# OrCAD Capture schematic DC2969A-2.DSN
size B
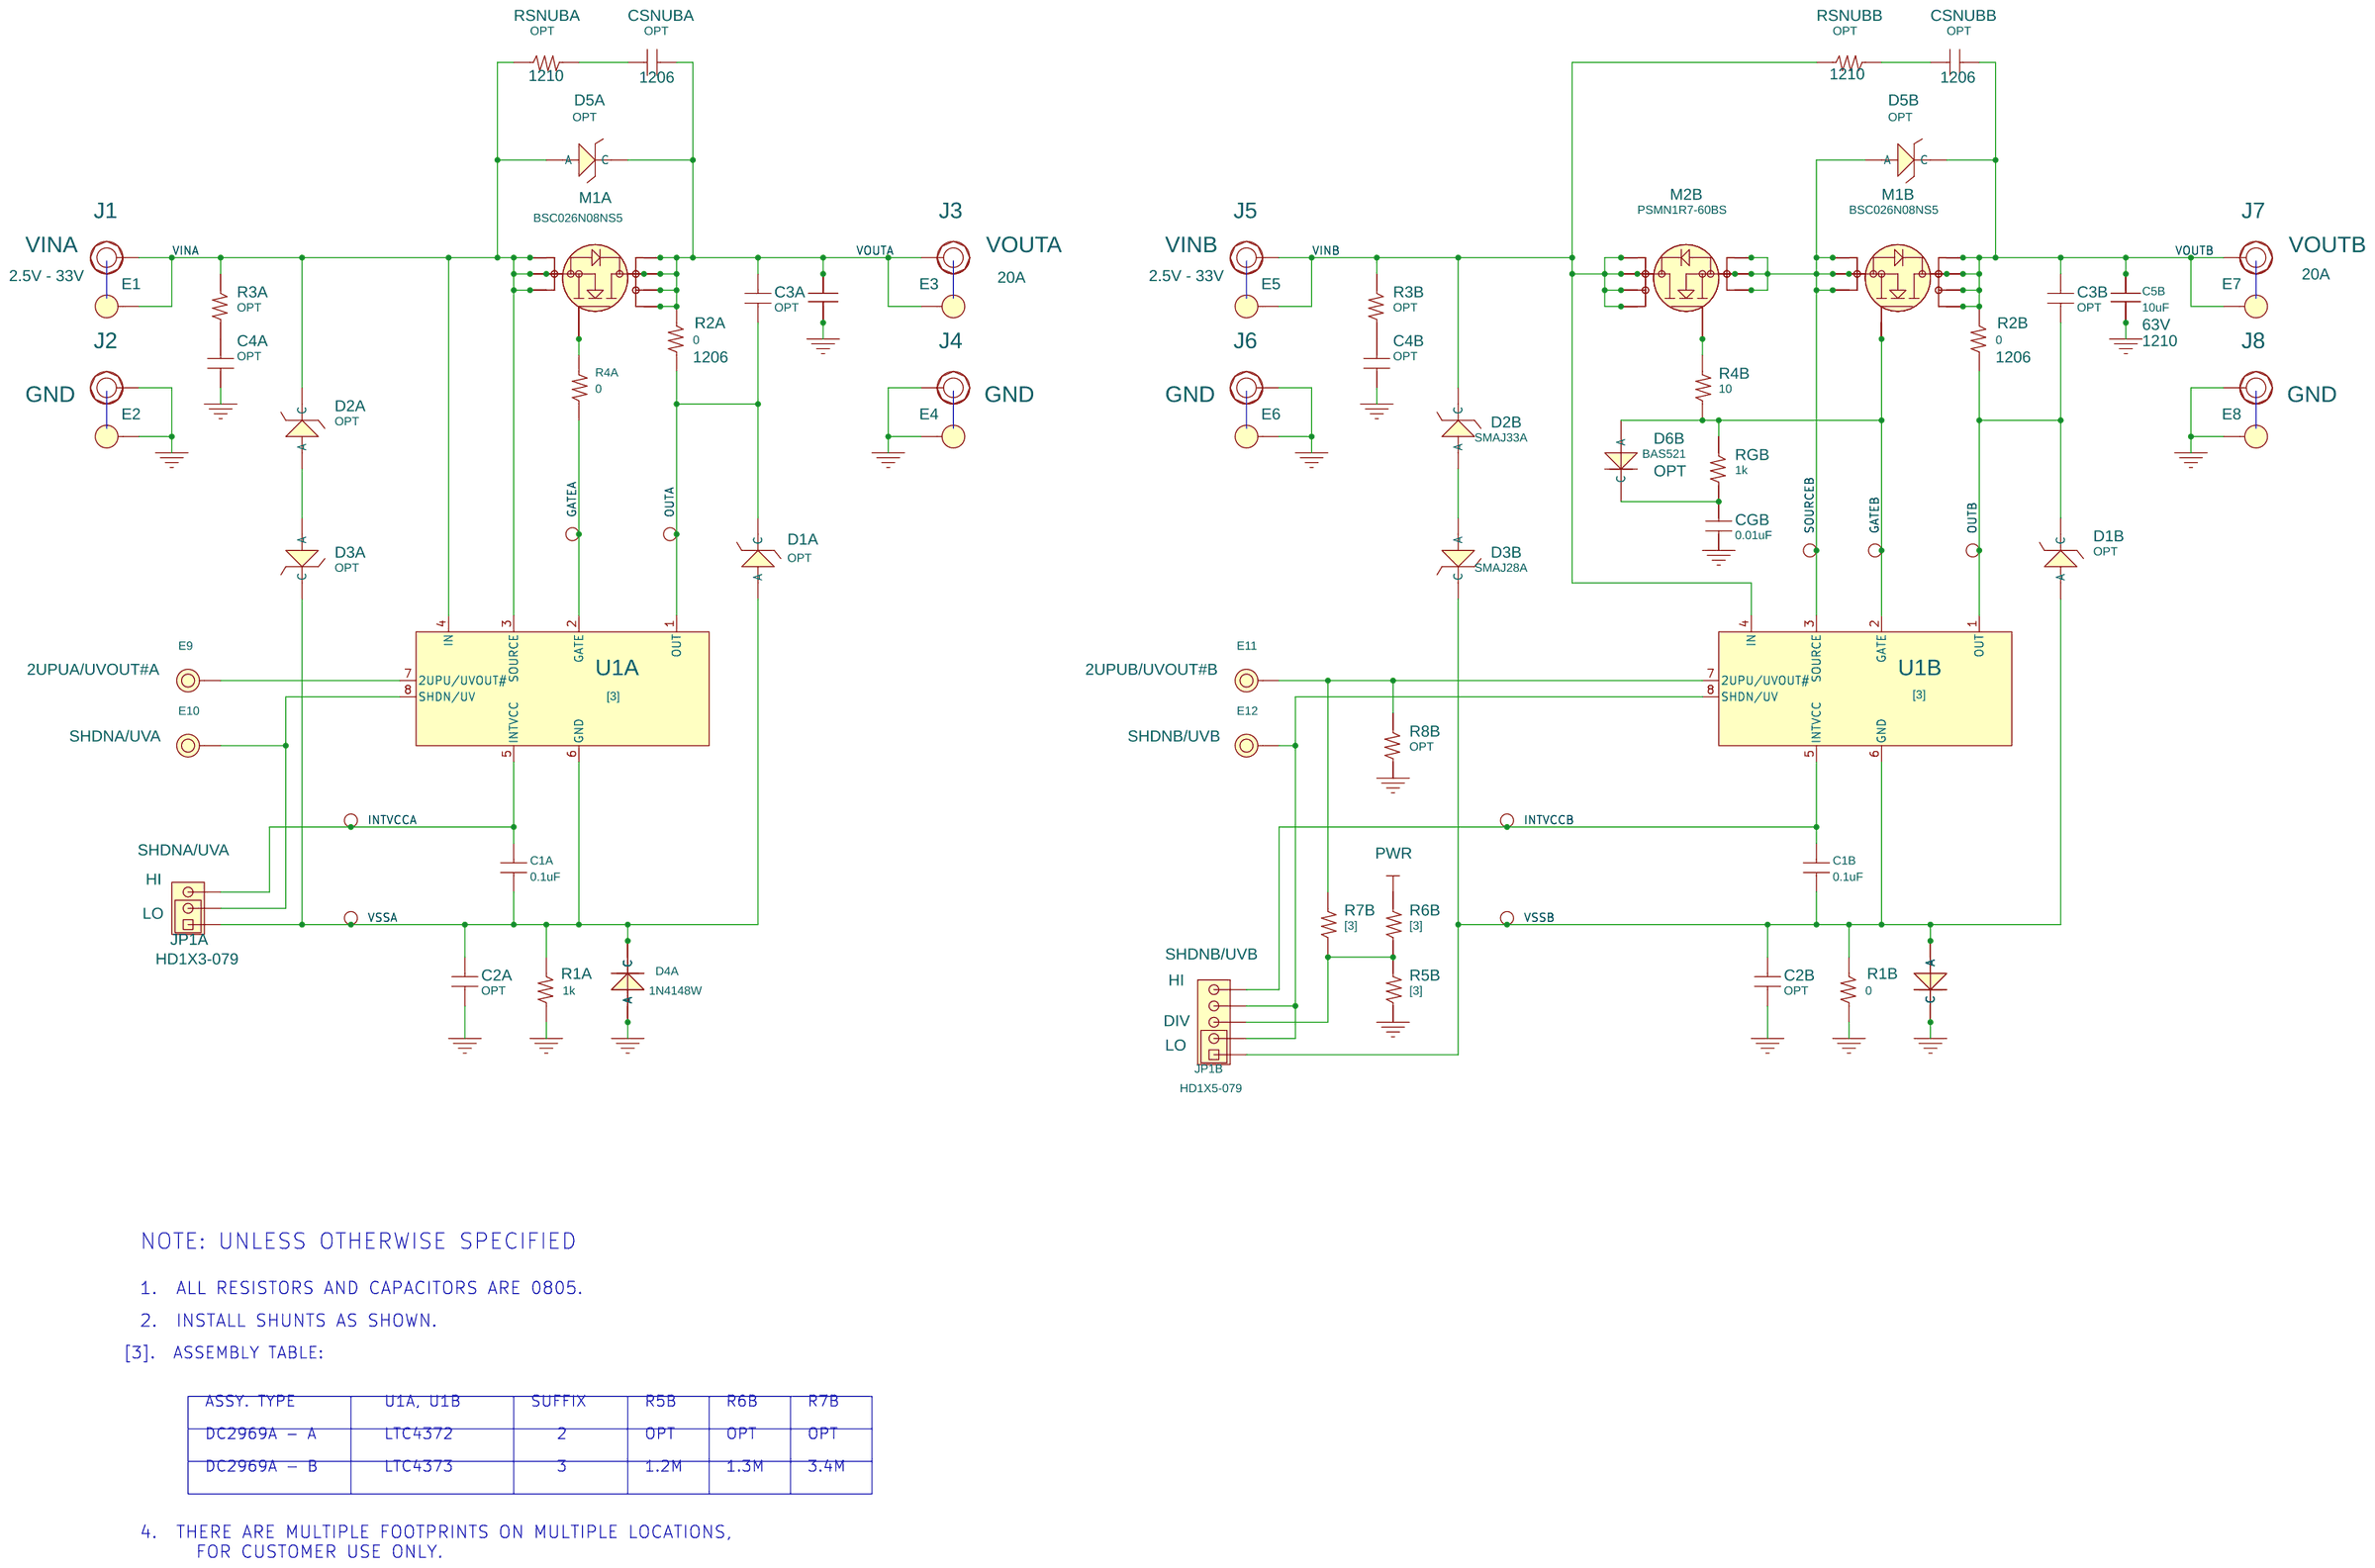
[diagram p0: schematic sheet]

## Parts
C1A  0.1uF  [CC0805N]
C1B  0.1uF  [CC0805N]
C2A  OPT  [0805]
C2B  OPT  [0805]
C3A  OPT  [0805]
C3B  OPT  [0805]
C4A  OPT  [0805]
C4B  OPT  [0805]
C5A  10uF  [CC1210N]
C5AA  OPT  [1210-NS]
C5B  10uF  [CC1210N]
C5BB  OPT  [1210-NS]
CGB  0.01uF  [0805]
CSNUBA  OPT  [1206]
CSNUBB  OPT  [1206]
D1A  OPT  [SMA-DIODE]
D1B  OPT  [SMA-DIODE]
D2A  OPT  [SMA-DIODE]
D2B  SMAJ33A  [SMA-DIODE]
D3A  OPT  [SMA-DIODE]
D3B  SMAJ28A  [SMA-DIODE]
D4A  1N4148W  [SOD-123N]
D4AA  1N4148W  [SMA-DIODE-NS]
D4B  1N4148W  [SOD-123N]
D4BB  1N4148W  [SMA-DIODE-NS]
D5A  OPT  [SMA-DIODE]
D5B  OPT  [SMA-DIODE]
D6B  BAS521  [SOD523]
E1  MILL-MAX-2501  [MILL-MAX-2501]
E2  MILL-MAX-2501  [MILL-MAX-2501]
E3  MILL-MAX-2501  [MILL-MAX-2501]
E4  MILL-MAX-2501  [MILL-MAX-2501]
E5  MILL-MAX-2501  [MILL-MAX-2501]
E6  MILL-MAX-2501  [MILL-MAX-2501]
E7  MILL-MAX-2501  [MILL-MAX-2501]
E8  MILL-MAX-2501  [MILL-MAX-2501]
E9  MIL-MAX-2308  [MILL-MAX-2308]
E10  MIL-MAX-2308  [MILL-MAX-2308]
E11  MIL-MAX-2308  [MILL-MAX-2308]
E12  MIL-MAX-2308  [MILL-MAX-2308]
GATEA  E-100-25  [PAD100-25]
GATEB  E-100-25  [PAD100-25]
INTVCCA  E-100-25  [PAD100-25]
INTVCCB  E-100-25  [PAD100-25]
J1  BANANA JACK  [KEY-575-4]
J2  BANANA JACK  [KEY-575-4]
J3  BANANA JACK  [KEY-575-4]
J4  BANANA JACK  [KEY-575-4]
J5  BANANA JACK  [KEY-575-4]
J6  BANANA JACK  [KEY-575-4]
J7  BANANA JACK  [KEY-575-4]
J8  BANANA JACK  [KEY-575-4]
JP1A  HDR.  [HD1X3-079]
JP1B  HD1X5-079  [HD1X5-079]
M1A  BSC026N08NS5  [PG-TDSON8]
M1A-B-SO8  BSC026N08NS5  [PG-TDSON8-NS]
M1A-OPT-B  D2PAK-DPAK-SO8POWERPAK  [D2PAK-DPAK-SO8POWERPAK-NS]
M1A-OPT-T  D2PAK-DPAK-SO8POWERPAK  [D2PAK-DPAK-SO8POWERPAK-NS]
M1B  BSC026N08NS5  [PG-TDSON8]
M1B-B-SO8  BSC026N08NS5  [PG-TDSON8-NS]
M1B-OPT-B  D2PAK-DPAK-SO8POWERPAK  [D2PAK-DPAK-SO8POWERPAK-NS]
M1B-OPT-T  D2PAK-DPAK-SO8POWERPAK  [D2PAK-DPAK-SO8POWERPAK-NS]
M2B  PSMN1R7-60BS  [D2PAK]
M2B-B-SO8  BSC026N08NS5  [PG-TDSON8-NS]
M2B-OPT-B  D2PAK-DPAK-SO8POWERPAK  [D2PAK-DPAK-SO8POWERPAK-NS]
M2B-OPT-T  D2PAK-DPAK-SO8POWERPAK  [D2PAK-DPAK-SO8POWERPAK-NS]
M2B-T-SO8  BSC026N08NS5  [PG-TDSON8-NS]
OUTA  E-100-25  [PAD100-25]
OUTB  E-100-25  [PAD100-25]
R1A  1k  [1206-0805]
R1B  0  [1206-0805]
R2A  0  [1206]
R2B  0  [1206]
R3A  OPT  [0805]
R3B  OPT  [0805]
R4A  0  [CR0805N]
R4B  10  [0805]
R5B  [3]  [0805]
R6B  [3]  [0805]
R7B  [3]  [0805]
R8B  OPT  [0805]
RGB  1k  [0805]
RSNUBA  OPT  [1210]
RSNUBB  OPT  [1210]
SMAA  OPT  [SMA-DIODE]
SMAB  OPT  [SMA-DIODE]
SOURCEB  E-100-25  [PAD100-25]
U1A  [3]  [MS8]
U1B  [3]  [MS8]
VSSA  E-100-25  [PAD100-25]
VSSB  E-100-25  [PAD100-25]

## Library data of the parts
C1A C1B = CAP_ALT: CAP.,0.1uF,X7R,25V,20%,0805; CLASS: DISCRETE; Dielectric Type: X7R; FPLIST: CC0805N,CC0805L,CC0805M; Inventory Qty: 198; Manufacturer: AVX; Manufacturer PN: 08053C104MAT2A; PART_NUMBER: 150-0305; Package Size: 0805; Rated Voltage: 25V; Tolerance: 20%
C2A C2B C3A C3B C4A C4B = CAP-NP: CAP., OPTION, 0805; CLASS: DISCRETE; FPLIST: CC0805N,CC0805L,CC0805M; PART_NUMBER: 150-3036; Package Type: SMD
C5A C5B = CAP: CAP.,10uF,X7R,63V,10%,1210; CLASS: DISCRETE; Dielectric Type: X7R; FPLIST: CC1210N,CC1210L,CC1210M; Inventory Qty: 6452; Manufacturer: Murata; Manufacturer PN: GRM32ER71J106KA12L; PART_NUMBER: 150-1321; Package Size: 1210; Rated Voltage: 63V; Tolerance: 10%
C5AA C5BB = CAP: CAP., OPTION, 1210; CLASS: DISCRETE; FPLIST: CC1210N,CC1210L,CC1210M; PART_NUMBER: 150-3035; Package Size: 1210; Package Type: SMD
CGB = CAP-NP: CAP.,0.01uF,X7R,100V,10%,0805; CLASS: DISCRETE; Dielectric Type: X7R; FPLIST: CC0805N,CC0805L,CC0805M; Inventory Qty: 13000; Manufacturer: AVX; Manufacturer PN: 08051C103KAT2A; PART_NUMBER: 150-2308; Package Type: SMD; Rated Voltage: 100V; Tolerance: 10%
CSNUBA CSNUBB = CAP-NP: CAP., OPTION, 1206; CLASS: DISCRETE; FPLIST: CC1206N,CC1206L,CC1206M; PART_NUMBER: 150-3160; Package Type: SMD
D1A D1B = DIODE_TVS_B: DIODE,TVS, SINGLE, UNI-DIRECT,33V,400W,SMA; CLASS: DISCRETE; FPLIST: SMA-N,SMA-L,SMA-M,SMA; Manufacturer: DIODES INC.; Manufacturer PN: SMAJ33A; Max Forward Current or Rated Power: 400W; PART_NUMBER: SMAJ33A; Package Type: SMA; Rated Voltage or Zener Voltage: 33V
D2A D3A D5A D5B = DIODE_TVS_B: DIODE, OPTION, TVS, SMA; CLASS: DISCRETE; FPLIST: SMA-N,SMA-L,SMA-M,SMA; PART_NUMBER: 210-0215; Package Type: SMA
D2B = DIODE_TVS_B: DIODE,TVS, SINGLE, UNI-DIRECT,33V,400W,SMA; CLASS: DISCRETE; FPLIST: SMA-N,SMA-L,SMA-M,SMA; Manufacturer: DIODES INC.; Max Forward Current or Rated Power: 400W; Package Type: SMA; Rated Voltage or Zener Voltage: 33V
D3B = DIODE_TVS_B: DIODE, OPTION, TVS, SMA; CLASS: DISCRETE; FPLIST: SMA-N,SMA-L,SMA-M,SMA; Package Type: SMA
D4A = DIODE_A: DIODE,SWITCHING,100V,300mA,SOD-123; CLASS: DISCRETE; FPLIST: SOD-123N,SOD-123L,SOD-123M; Inventory Qty: 3450; Manufacturer: DIODES INC.; Manufacturer PN: 1N4148W-7-F; Max Forward Current or Rated Power: 200mW; PART_NUMBER: 210-0214; Package Type: SOD-123; Rated Voltage or Zener Voltage: 100V
D4AA D4B D4BB = DIODE_A: DIODE,SWITCHING,100V,300mA,SOD-123; CLASS: DISCRETE; FPLIST: SOD-123N,SOD-123L,SOD-123M; Inventory Qty: 3450; Manufacturer: DIODES INC.; Manufacturer PN: 1N4148W-7-F; Max Forward Current or Rated Power: 200mW; OPT: OPT; PART_NUMBER: 210-0214; Package Type: SOD-123; Rated Voltage or Zener Voltage: 100V
D6B = DIODE_A: DIODE,SWITCHING,300V,250mA,SOD-523; CLASS: DISCRETE; FPLIST: SOD-523N,SOD-523L,SOD-523M; Inventory Qty: 6616; Manufacturer: DIODES INC.; Manufacturer PN: BAS521-7; Max Forward Current or Rated Power: 250mA; OPT: OPT; PART_NUMBER: 210-0122; Package Size: SC-79, SOD-523; Package Type: SOD-523; Rated Voltage or Zener Voltage: 300V
E1-E8 = E-094: TEST POINT,TURRET,0.064" MTG. HOLE,PCB 0.062" THICK; CLASS: IO; Inventory Qty: 832548; Manufacturer: MILL-MAX; Manufacturer PN: 2308-2-00-80-00-00-07-0; PART_NUMBER: 260-0004
E9 = E-064: 1ST PART FIELD: 2UPUA/UVOUT#A
E10 = E-064: 1ST PART FIELD: SHDNA/UVA
E11 = E-064: 1ST PART FIELD: 2UPUB/UVOUT#B
E12 = E-064: 1ST PART FIELD: SHDNB/UVB
GATEA GATEB INTVCCA INTVCCB OUTA OUTB SOURCEB VSSA VSSB = E-100-25
J1 = E-KEY-575: CONN.,BANANA JACK,FEMALE,THT,NON-INSULATED,SWAGE,0.218"; 1ST PART FIELD: VINA; 2ND PART FIELD: 2.5V - 33V; CLASS: IO; Inventory Qty: 178390; Manufacturer: KEYSTONE; Manufacturer PN: 575-4; PART_NUMBER: 250-0428
J2 J4 J6 J8 = E-KEY-575: CONN.,BANANA JACK,FEMALE,THT,NON-INSULATED,SWAGE,0.218"; 1ST PART FIELD: GND; CLASS: IO; Inventory Qty: 178390; Manufacturer: KEYSTONE; Manufacturer PN: 575-4; PART_NUMBER: 250-0428
J3 = E-KEY-575: CONN.,BANANA JACK,FEMALE,THT,NON-INSULATED,SWAGE,0.218"; 1ST PART FIELD: VOUTA; AMP: 20A; CLASS: IO; Inventory Qty: 178390; Manufacturer: KEYSTONE; Manufacturer PN: 575-4; PART_NUMBER: 250-0428
J5 = E-KEY-575: CONN.,BANANA JACK,FEMALE,THT,NON-INSULATED,SWAGE,0.218"; 1ST PART FIELD: VINB; 2ND PART FIELD: 2.5V - 33V; CLASS: IO; Inventory Qty: 178390; Manufacturer: KEYSTONE; Manufacturer PN: 575-4; PART_NUMBER: 250-0428
J7 = E-KEY-575: CONN.,BANANA JACK,FEMALE,THT,NON-INSULATED,SWAGE,0.218"; 1ST PART FIELD: VOUTB; AMP: 20A; CLASS: IO; Inventory Qty: 178390; Manufacturer: KEYSTONE; Manufacturer PN: 575-4; PART_NUMBER: 250-0428
JP1A = HD1X3: CONN.,HDR.,MALE,1x3,2mm,THT, STR,NO SUBS. ALLOWED; 1ST PART FIELD: SHDNA/UVA; 2ND PART FIELD: HI; 3RD PART FIELD: LO; CLASS: IO; Inventory Qty: 9908; Manufacturer: SAMTEC; Manufacturer PN: TMM-103-02-L-S; PART_NUMBER: 250-0638
JP1B = HD1X5-079: 1ST PART FIELD: SHDNB/UVB; 2ND PART FIELD: HI; 3RD PART FIELD: LO; DC2093A: DIV
M1A M1A-B-SO8 M1B M1B-B-SO8 M2B-B-SO8 M2B-T-SO8 = MOSFET_N-BSC026N08NS5-PG-TDSON8: XSTR.,MOSFET, N-CH,80V,100A,PG-TDSON-8; CLASS: DISCRETE; Manufacturer: INFINEON; PART_NUMBER: Infineon, BSC026N08NS5; Package Size: 8-PowerTDFN; Package Type: PG-TDSON-8; Polarity: N-Channel; Rated Voltage: 80V
M1A-OPT-B M1A-OPT-T M1B-OPT-B M1B-OPT-T M2B-OPT-B M2B-OPT-T = MOSFET-D2PAK-DPAK-SO8POWERPAK
M2B = MOSFET-PSMN1R7-D2PAK: XSTR.,MOSFET N-CHAN,30V,120A,D2PAK; CLASS: DISCRETE; Inventory Qty: 1188; Manufacturer: NEXPERIA; Manufacturer PN: PSMN; PART_NUMBER: Nexperia, PSMN1R7-60BS; Rated Voltage: 30V
R1A R1B = R: RES.,0 OHM,1/2W,1206,PULSE PROOF HIGH PWR, AEC-Q200; CLASS: DISCRETE; FPLIST: CR1206N,CR1206L,CR1206M; Inventory Qty: 7204; Manufacturer: VISHAY; Manufacturer PN: CRCW12060000Z0EAHP; PART_NUMBER: 100-2119; Package Size: 1206; Rated Power: 1/2W
R2A R2B = R: RES.,0 OHM,1/2W,1206,PULSE PROOF HIGH PWR, AEC-Q200; CLASS: DISCRETE; FPLIST: CR1206N,CR1206L,CR1206M; Inventory Qty: 7204; Manufacturer: VISHAY; Manufacturer PN: CRCW12060000Z0EAHP; PART_NUMBER: 100-2119; Rated Power: 1/2W
R3A R3B R8B = R: RES., OPTION, 0805; CLASS: DISCRETE; FPLIST: CR0805N,CR0805L,CR0805M; PART_NUMBER: 100-2558
R4A = RES_ALT: RES.,0 OHM,1/8W,0805; CLASS: DISCRETE; FPLIST: CR0805N,CR0805L,CR0805M; Inventory Qty: 86985; Manufacturer: VISHAY; Manufacturer PN: CRCW08050000Z0EA; PART_NUMBER: 100-0024; Package Size: 0805; Rated Power: 1/8W
R4B R5B R6B R7B = R: RES.,10 OHMS,5%,1/8W,0805,AEC-Q200; CLASS: DISCRETE; FPLIST: CR0805N,CR0805L,CR0805M; Inventory Qty: 28575; Manufacturer: NIC; Manufacturer PN: NRC10J100TRF; PART_NUMBER: 100-0229; Rated Power: 1/8W; Temperature Coefficient: 200ppm/C; Tolerance: 5%
RGB = R: RES.,1k OHMS,5%,1/8W,0805; CLASS: DISCRETE; FPLIST: CR0805N,CR0805L,CR0805M; Inventory Qty: 14216; Manufacturer: NIC; Manufacturer PN: NRC10J102TRF; PART_NUMBER: 100-0401; Rated Power: 1/8W; Temperature Coefficient: +/-100PPM; Tolerance: 5%
RSNUBA RSNUBB = R: RES., OPTION, 1210; CLASS: DISCRETE; FPLIST: CR1210N,CR1210L,CR1210M; PART_NUMBER: 100-0100
SMAA SMAB = CAP: CLASS: DISCRETE; Package Type: SMD
U1A U1B = LTC4372HMS8-MS8: IC, IDEAL DIODE CTLR, 8-MSOP; CLASS: IC; Manufacturer: ANALOG DEVICES; Manufacturer PN: LTC4372HMS8#TRPBF; PART_NUMBER: ADI, LTC4372; Package Size: MS-8

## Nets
GND: C2A.2 C2B.2 C4A.2 C4B.2 C5A.2 C5AA.2 C5B.2 C5BB.2 CGB.2 D4A.2(A) D4AA.2(A) D4B.1(C) D4BB.1(C) E2.1(A) E4.1(A) E6.1(A) E8.1(A) J2.1 J4.1 J6.1 J8.1 R1A.2 R1B.2 R5B.1 R8B.2 SMAA.2 SMAB.2
VINA: D2A.1(C) D5A.2(A) E1.1(A) J1.1 M1A.1 M1A.2 M1A.3 M1A-B-SO8.1 M1A-B-SO8.2 M1A-B-SO8.3 M1A-OPT-B.3 M1A-OPT-T.3 R3A.1 RSNUBA.1 U1A.3(SOURCE) U1A.4(IN)
VINB: D2B.1(C) E5.1(A) J5.1 M2B.2 M2B-B-SO8.5 M2B-B-SO8.6 M2B-B-SO8.7 M2B-B-SO8.8 M2B-OPT-B.2 M2B-OPT-T.2 M2B-T-SO8.5 M2B-T-SO8.6 M2B-T-SO8.7 M2B-T-SO8.8 R3B.1 R6B.2 RSNUBB.1 U1B.4(IN)
VSSA: C1A.2 C2A.1 D1A.2(A) D3A.1(C) D4A.1(C) D4AA.1(C) JP1A.1 R1A.1 U1A.6(GND) VSSA.1
VSSB: C1B.2 C2B.1 D1B.2(A) D3B.1(C) D4B.2(A) JP1B.1 R1B.1 U1B.6(GND) VSSB.1
GATEA: GATEA.1 R4A.1 U1A.2(GATE)
GATEB: D6B.2(A) GATEB.1 M1B.4 M1B-B-SO8.4 M1B-OPT-B.1 M1B-OPT-B.4 M1B-OPT-T.1 M1B-OPT-T.4 R4B.1 RGB.1 U1B.2(GATE)
INTVCCA: C1A.1 INTVCCA.1 JP1A.3 U1A.5(INTVCC)
INTVCCB: C1B.1 INTVCCB.1 JP1B.5 U1B.5(INTVCC)
OUTA: C3A.2 D1A.1(C) OUTA.1 R2A.2 U1A.1(OUT)
OUTB: C3B.2 D1B.1(C) OUTB.1 R2B.2 U1B.1(OUT)
SOURCEB: D5B.2(A) M1B.1 M1B.2 M1B.3 M1B-B-SO8.1 M1B-B-SO8.2 M1B-B-SO8.3 M1B-OPT-B.3 M1B-OPT-T.3 M2B.3 M2B-B-SO8.1 M2B-B-SO8.2 M2B-B-SO8.3 M2B-OPT-B.3 M2B-OPT-T.3 M2B-T-SO8.1 M2B-T-SO8.2 M2B-T-SO8.3 SOURCEB.1 U1B.3(SOURCE)
VOUTA: C3A.1 C5A.1 CSNUBA.2 D5A.1(C) E3.1(A) J3.1 M1A.5 M1A.6 M1A.7 M1A.8 M1A-B-SO8.5 M1A-B-SO8.6 M1A-B-SO8.7 M1A-B-SO8.8 M1A-OPT-B.2 M1A-OPT-T.2 R2A.1 SMAA.1
VOUTB: C3B.1 C5B.1 C5BB.1 CSNUBB.2 D5B.1(C) E7.1(A) J7.1 M1B.5 M1B.6 M1B.7 M1B.8 M1B-B-SO8.5 M1B-B-SO8.6 M1B-B-SO8.7 M1B-B-SO8.8 M1B-OPT-B.2 M1B-OPT-T.2 R2B.1 SMAB.1
N00296: M1A.4 M1A-B-SO8.4 M1A-OPT-B.1 M1A-OPT-B.4 M1A-OPT-T.1 M1A-OPT-T.4 R4A.2
N06898: E10.1(A) JP1A.2 U1A.8(SHDN/UV)
N06902: E9.1(A) U1A.7(2UPU/UVOUT#)
N10189: D2A.2(A) D3A.2(A)
N13285: CSNUBA.1 RSNUBA.2
N171454: CSNUBB.1 RSNUBB.2
N171868: D2B.2(A) D3B.2(A)
N172002: E11.1(A) R7B.2 R8B.1 U1B.7(2UPU/UVOUT#)
N172016: CGB.1 D6B.1(C) RGB.2
N172040: E12.1(A) JP1B.2 JP1B.4 U1B.8(SHDN/UV)
N870836: JP1B.3 R5B.2 R6B.1 R7B.1
N913982: M2B.1 M2B-B-SO8.4 M2B-OPT-B.1 M2B-OPT-B.4 M2B-OPT-T.1 M2B-OPT-T.4 M2B-T-SO8.4 R4B.2
N922618: C4A.1 R3A.2
N922620: C4B.1 R3B.2

Not connected (* = marked no-connect by the designer): C5AA 1; D4BB 2(A)

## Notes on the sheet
- NOTE: UNLESS OTHERWISE SPECIFIED
- 1.  ALL RESISTORS AND CAPACITORS ARE 0805.
- 2.  INSTALL SHUNTS AS SHOWN.
- [3].  ASSEMBLY TABLE:
- ASSY. TYPE
- U1A, U1B
- SUFFIX
- R5B
- R6B
- R7B
- DC2969A - A
- LTC4372
- 2
- OPT
- OPT
- OPT
- DC2969A - B
- LTC4373
- 3
- 1.2M
- 1.3M
- 3.4M
- 4.  THERE ARE MULTIPLE FOOTPRINTS ON MULTIPLE LOCATIONS,
        FOR CUSTOMER USE ONLY.
